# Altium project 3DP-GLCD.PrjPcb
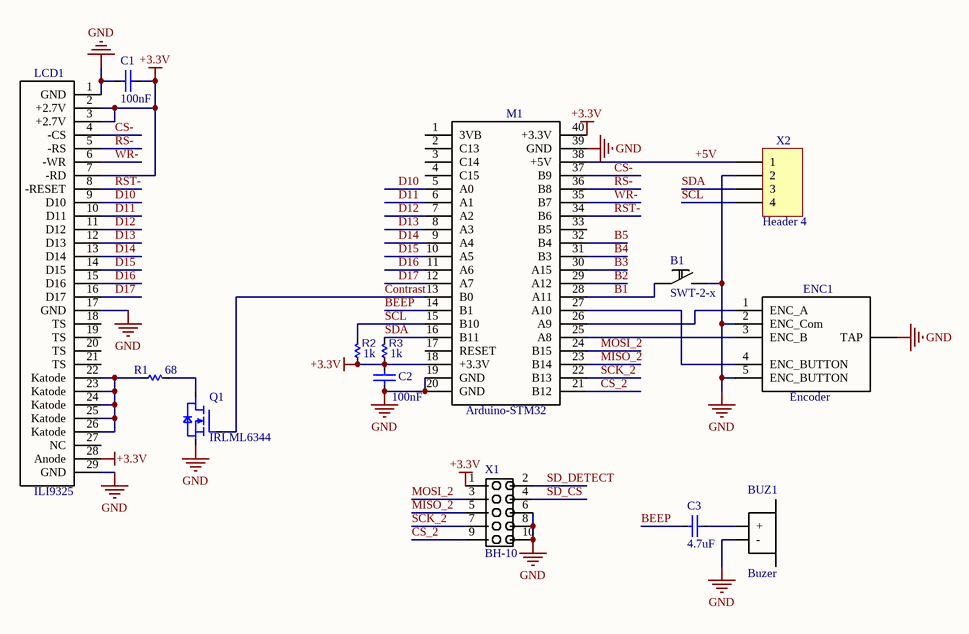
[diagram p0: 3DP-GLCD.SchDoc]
1 sheet, 14 parts. Net scope: global (net labels, ports and power ports of the same name join across sheets).
Board file: 3DP-GLCD.PcbDoc

## Sheet 3DP-GLCD.SchDoc: TFT GLCD Adapter
size A4; Engineer: Serj_K; Revision: 1.1; SheetNumber: 1; SheetTotal: 1

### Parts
B1  SWT-2-x  [SWT-2-x]
BUZ1  Buzer  [Buzer_12xx]
C1  value 100nF  [C0805_Murata]  (hidden comment: Cap)
C2  value 100nF  [C0805_Murata]  (hidden comment: Cap)
C3  value 4.7uF  [C1206_Murata]  (hidden comment: Cap)
ENC1  Encoder  [Encoder_bot]
LCD1  ILI9325  [LCD-ILI9325-29pin-top]
M1  Arduino-STM32  [ARDUINO-STM32]
Q1  IRLML6344  [SOT23-3_IR]
R1  value 68  [R0805_UniOhm]  (hidden comment: R)
R2  value 1k  [R0805_UniOhm]  (hidden comment: R)
R3  value 1k  [R0805_UniOhm]  (hidden comment: R)
X1  BH-10  [BH-10]
X2  Header 4  [HDR1X4]

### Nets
+3.3V: C1.1 C2.1 LCD1.2(+2.7V) LCD1.3(+2.7V) LCD1.7(-RD) LCD1.28(Anode) M1.18(+3.3V) M1.40(+3.3V) R2.1 R3.1 X1.1
GND: B1.2 BUZ1.2(-) C1.2 C2.2 ENC1.0(TAP) ENC1.2(ENC_Com) ENC1.5(ENC_BUTTON) LCD1.1(GND) LCD1.17(GND) LCD1.29(GND) M1.19(GND) M1.20(GND) M1.39(GND) Q1.2(S) X1.6 X1.8 X1.10 X2.2
+5V: M1.38(+5V) X2.1
B1: B1.1 M1.28(A11)
B2: M1.29(A12)
B3: M1.30(A15)
B4: M1.31(B3)
B5: M1.32(B4)
BEEP: C3.1 M1.14(B1)
Contrast: M1.13(B0) Q1.1(G)
CS-: LCD1.4(-CS) M1.37(B9)
CS_2: M1.21(B12) X1.9
D10: LCD1.9(D10) M1.5(A0)
D11: LCD1.10(D11) M1.6(A1)
D12: LCD1.11(D12) M1.7(A2)
D13: LCD1.12(D13) M1.8(A3)
D14: LCD1.13(D14) M1.9(A4)
D15: LCD1.14(D15) M1.10(A5)
D16: LCD1.15(D16) M1.11(A6)
D17: LCD1.16(D17) M1.12(A7)
MISO_2: M1.23(B14) X1.5
MOSI_2: M1.24(B15) X1.3
RS-: LCD1.5(-RS) M1.36(B8)
RST-: LCD1.8(-RESET) M1.34(B6)
SCK_2: M1.22(B13) X1.7
SCL: M1.15(B10) R2.2 X2.4
SD_CS: X1.4
SD_DETECT: X1.2
SDA: M1.16(B11) R3.2 X2.3
WR-: LCD1.6(-WR) M1.35(B7)
NetBUZ1_1: BUZ1.1(+) C3.2
NetENC1_1: ENC1.1(ENC_A) M1.26(A9)
NetENC1_3: ENC1.3(ENC_B) M1.25(A8)
NetENC1_4: ENC1.4(ENC_BUTTON) M1.27(A10)
NetLCD1_22: LCD1.22(Katode) LCD1.23(Katode) LCD1.24(Katode) LCD1.25(Katode) LCD1.26(Katode) R1.1
NetQ1_3: Q1.3(D) R1.2

Not connected (* = marked no-connect by the designer): LCD1 18(TS) 19(TS) 20(TS) 21(TS) 27(NC); M1 1(3VB) 2(C13) 3(C14) 4(C15) 17(RESET) 33(B5)

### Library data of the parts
C1 C2 = GRM21BR71H104KA01L: PartName: GRM21; Part Label: C0805 100nF 10% X7R 50V; Manufacturer: muRata; Voltage: 50V; Tolerance: 10 %; Device: C; ShortName: C0805
C3 = GRM31CR71H475KA12L: PartName: GRM31; Part Label: C1206 4.7uF 10% X7R 50V; Manufacturer: muRata; Voltage: 50V; Tolerance: 10 %; Device: C; ShortName: C1206
ENC1 = Encoder: Rotary Encoder with button
LCD1 = LCD-ILI9325-29pin: TFT LCD
Q1 = IRLML6344TRPBF: 30 V, 5.0 A, 0.029 Ohm Single N-Channel HEXFET Power MOSFET; Manufacturer: International Rectifier; Device: Q; ShortName: NMOS
R1 = 0805S8F4700T50: PartName: 0805S; Part Label: R0805 470 1% TC100 150V; Manufacturer: uniOhm; TempCo: 100 ppm; Tolerance: 1 %; ShortName: R0805
R2 R3 = R: Resistor
X1 = BH-10_2
X2 = Header 4: Header, 4-Pin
